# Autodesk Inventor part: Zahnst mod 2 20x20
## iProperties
Created: 2006-11
Part Number: Zahnst mod 2 20x20
Cost Center: 0,357 kg
Material: Stahl (schweißbar)
Document SubType Name: Modeling
Designer: Schmidt
Authority: 45428 mm^3
Density: 7.86 g/cm^3
SaveDate: 2006-11-03
SaveTime: 00:32
TotalMass: 0,357 kg
TotalVolume: 45428 mm^3
Author: Schmidt
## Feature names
1. Basis1
2. Extrusion2
3. Bohrung2 [Hole]
4. Rechteckige Anordnung1 [Rectangular Pattern]
